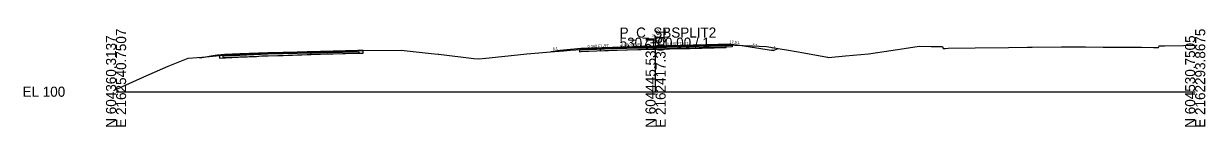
# Model space of a CAD drawing. Extents: x -26 to 1303, y -10 to 12033.
# Drawn here: x 974.3 to 1302.8, y 1490.3 to 1517.8 of the extents above; entities that cross this region are included whole.
import ezdxf

# ---------------------------------------------------------------- set-up
doc = ezdxf.new("R2010")
doc.units = 0
for name, color, linetype in [('RD_GPK_XS_Cell', 7, 'Continuous'), ('RD_XS_Base', 7, 'Continuous'), ('RD_XS_ExGround', 7, 'Continuous'), ('RD_XS_ExPaveRet', 7, 'Continuous'), ('RD_XS_Greenside', 7, 'Continuous'), ('RD_XS_Pave', 7, 'Continuous'), ('RD_XS_PaveOvlay_CP', 7, 'Continuous'), ('RD_XS_TieSlope', 7, 'Continuous'), ('RD_XS_TX_Elev_EX', 7, 'Continuous'), ('RD_XS_TX_Elev_PR', 7, 'Continuous'), ('RD_XS_TX_ShdSlope', 7, 'Continuous'), ('RD_XS_TX_Slope', 7, 'Continuous')]:
    doc.layers.add(name, color=color, linetype=linetype)

msp = doc.modelspace()

# ---------------------------------------------------------------- linework, layer by layer
at = {"layer": 'RD_GPK_XS_Cell'}
for p, q in [((1150, 1500), (1150, 1515)), ((1000, 1500), (1150, 1500)), ((1150, 1500), (1300, 1500))]:
    msp.add_line(p, q, dxfattribs=at)
at = {"layer": 'RD_XS_Base'}
for p, q in [((1129.34, 1511.62), (1128.84, 1511.6)), ((1128.84, 1511.6), (1128.84, 1511.6)), ((1128.84, 1511.6), (1128.84, 1511.1)), ((1138, 1511.97), (1129.34, 1511.62)), ((1129.34, 1511.62), (1129.34, 1511.62)), ((1129.34, 1511.12), (1138, 1511.47)), ((1150, 1512.3), (1138, 1511.97)), ((1138, 1511.97), (1138, 1511.97)), ((1138, 1511.47), (1150, 1511.8)), ((1138, 1511.47), (1138, 1511.47)), ((1150, 1512.3), (1170.78, 1512.89)), ((1150, 1511.8), (1150, 1512.46)), ((1150, 1512.46), (1150, 1512.46)), ((1150, 1512.46), (1150, 1512.46)), ((1150, 1512.46), (1150, 1512.3)), ((1171.28, 1512.4), (1150, 1511.8)), ((1150, 1512.3), (1150, 1512.3)), ((1150, 1511.8), (1150, 1512.3)), ((1150, 1512.3), (1150, 1512.3)), ((1150, 1512.3), (1150, 1512.3)), ((1150, 1511.8), (1150, 1511.8)), ((1162, 1512.64), (1162, 1512.64)), ((1162, 1512.64), (1162, 1512.64)), ((1162, 1512.14), (1162, 1512.14)), ((1162, 1512.14), (1162, 1512.14)), ((1170.78, 1512.89), (1170.78, 1512.89)), ((1171.28, 1512.9), (1171.28, 1512.4)), ((1171.28, 1512.87), (1171.28, 1512.87)), ((1029.88, 1509.98), (1029.7, 1509.97)), ((1029.7, 1509.97), (1029.7, 1509.65)), ((1029.7, 1509.65), (1029.7, 1509.47)), ((1029.7, 1509.47), (1029.88, 1509.48)), ((1030.2, 1509.99), (1029.88, 1509.98)), ((1029.88, 1509.48), (1030.2, 1509.49)), ((1034.45, 1510.16), (1030.2, 1509.99)), ((1030.2, 1509.49), (1034.45, 1509.66)), ((1042.2, 1510.47), (1034.45, 1510.16)), ((1034.45, 1509.66), (1042.2, 1509.97)), ((1046.47, 1510.58), (1042.2, 1510.47)), ((1042.2, 1509.97), (1046.47, 1510.08)), ((1054.2, 1510.78), (1046.47, 1510.58)), ((1046.47, 1510.08), (1054.2, 1510.28)), ((1054.2, 1510.78), (1067.49, 1511.07)), ((1054.2, 1510.28), (1054.2, 1510.94)), ((1054.2, 1510.94), (1054.2, 1510.94)), ((1054.2, 1510.94), (1054.2, 1510.94)), ((1054.2, 1510.94), (1054.2, 1510.78)), ((1054.2, 1510.78), (1054.2, 1510.78)), ((1054.2, 1510.28), (1054.2, 1510.78)), ((1054.2, 1510.78), (1054.2, 1510.78)), ((1054.2, 1510.78), (1054.2, 1510.78)), ((1067.49, 1510.57), (1054.2, 1510.28)), ((1054.2, 1510.28), (1054.2, 1510.28)), ((1066.99, 1511.06), (1066.99, 1511.06)), ((1067.49, 1511.07), (1067.49, 1510.57)), ((1067.49, 1511.04), (1067.49, 1511.04)), ((1067.49, 1510.54), (1067.49, 1510.54)), ((1067.49, 1510.54), (1067.49, 1510.54)), ((1128.84, 1511.1), (1129.34, 1511.12)), ((1129.34, 1511.12), (1129.34, 1511.12))]:
    msp.add_line(p, q, dxfattribs=at)
at = {"layer": 'RD_XS_ExGround'}
msp.add_lwpolyline([(1000, 1500.62), (1001.8, 1501.41), (1008.58, 1504.51), (1009.22, 1504.79), (1014.52, 1507.1), (1020.09, 1509.3), (1025.01, 1509.7), (1028.72, 1510.03), (1033.84, 1510.29), (1039.07, 1510.5), (1040.42, 1510.66), (1041.32, 1510.69), (1042.18, 1510.73), (1053.16, 1511.05), (1056.82, 1511.18), (1067.32, 1511.43), (1068.74, 1511.46), (1068.78, 1511.46), (1079.23, 1511.51), (1087.65, 1510.63), (1089.57, 1510.45), (1089.78, 1510.42), (1099.49, 1509.24), (1100.86, 1509.09), (1102.81, 1509.28), (1105.47, 1509.57), (1114.2, 1510.49), (1121.85, 1511.13), (1124.48, 1511.35), (1126.3, 1511.5), (1129.35, 1511.71), (1134.57, 1512.07), (1139.36, 1512.24), (1145.08, 1512.46), (1146.02, 1512.5), (1149.98, 1512.58), (1150.08, 1512.58), (1150.08, 1512.58), (1150.13, 1512.58), (1153.88, 1512.65), (1159.25, 1512.73), (1159.52, 1512.74), (1169.63, 1513.01), (1176.74, 1512.72), (1180.83, 1512.56), (1184.06, 1511.97), (1186.98, 1511.5), (1191.22, 1510.79), (1197.82, 1509.56), (1198.05, 1509.52), (1202.75, 1509.96), (1209.22, 1510.5), (1215.43, 1511.43), (1220.33, 1512.2), (1223.25, 1512.61), (1226.61, 1512.54), (1229.79, 1512.49), (1229.86, 1512.25), (1229.94, 1511.99), (1230.61, 1512.02), (1231.35, 1512.04), (1238.83, 1512.14), (1248.09, 1512.28), (1253.38, 1512.32), (1254.7, 1512.33), (1262.84, 1512.4), (1266.31, 1512.42), (1269.55, 1512.44), (1274.45, 1512.34), (1275.65, 1512.33), (1280.56, 1512.38), (1282.43, 1512.36), (1285.1, 1512.33), (1288.43, 1512.29), (1288.81, 1512.28), (1289.85, 1512.24), (1289.96, 1512.61), (1290, 1512.74), (1291.46, 1512.75), (1296.8, 1512.77), (1300, 1512.92)], dxfattribs=at)
at = {"layer": 'RD_XS_ExPaveRet'}
for points in [[(1068.74, 1511.46), (1068.74, 1511.46), (1068.74, 1511.46), (1067.29, 1511.43), (1067.27, 1511.43), (1056.84, 1511.18), (1056.82, 1511.18), (1053.26, 1511.05), (1053.16, 1511.05), (1042.27, 1510.73), (1042.19, 1510.73), (1041.33, 1510.69), (1041.32, 1510.69), (1040.42, 1510.66), (1040.41, 1510.66), (1039.07, 1510.5), (1039.07, 1510.5), (1033.93, 1510.3), (1033.84, 1510.29), (1028.76, 1510.04), (1028.72, 1510.03), (1028.72, 1510.03), (1028.72, 1510.03), (1028.72, 1510.02), (1028.72, 1509.28), (1028.72, 1509.28), (1028.72, 1509.28), (1028.76, 1509.29), (1033.84, 1509.54), (1033.93, 1509.55), (1039.07, 1509.75), (1039.07, 1509.75), (1040.41, 1509.91), (1040.42, 1509.91), (1041.32, 1509.94), (1041.33, 1509.94), (1042.19, 1509.98), (1042.27, 1509.98), (1053.16, 1510.3), (1053.26, 1510.3), (1056.82, 1510.43), (1056.84, 1510.43), (1067.27, 1510.68), (1067.29, 1510.68), (1068.74, 1510.71), (1068.74, 1510.71), (1068.74, 1510.71), (1068.74, 1510.71), (1068.74, 1510.71), (1068.74, 1511.46), (1068.74, 1511.46)], [(1068.74, 1511.46), (1068.74, 1511.46), (1067.29, 1511.43), (1067.27, 1511.43), (1056.84, 1511.18), (1056.82, 1511.18), (1053.26, 1511.05), (1053.16, 1511.05), (1042.27, 1510.73), (1042.19, 1510.73), (1041.33, 1510.69), (1041.32, 1510.69), (1040.42, 1510.66), (1040.41, 1510.66), (1039.07, 1510.5), (1039.07, 1510.5), (1033.93, 1510.3), (1033.84, 1510.29), (1028.76, 1510.04), (1028.72, 1510.03), (1028.72, 1510.03), (1028.72, 1510.02), (1028.72, 1509.28), (1028.72, 1509.28), (1028.76, 1509.29), (1033.84, 1509.54), (1033.93, 1509.55), (1039.07, 1509.75), (1039.07, 1509.75), (1040.41, 1509.91), (1040.42, 1509.91), (1041.32, 1509.94), (1041.33, 1509.94), (1042.19, 1509.98), (1042.27, 1509.98), (1053.16, 1510.3), (1053.26, 1510.3), (1056.82, 1510.43), (1056.84, 1510.43), (1067.27, 1510.68), (1067.29, 1510.68), (1068.74, 1510.71), (1068.74, 1510.71), (1068.74, 1510.71), (1068.74, 1510.71), (1068.74, 1511.46), (1068.74, 1511.46)], [(1169.63, 1513.01), (1159.52, 1512.74), (1159.25, 1512.73), (1159.25, 1512.73), (1153.88, 1512.65), (1153.88, 1512.65), (1150.13, 1512.58), (1150.13, 1512.58), (1150.08, 1512.58), (1150.08, 1512.58), (1149.98, 1512.58), (1146.02, 1512.5), (1146.02, 1512.5), (1145.08, 1512.46), (1145.08, 1512.46), (1145.08, 1512.46), (1139.36, 1512.24), (1139.36, 1512.24), (1134.57, 1512.07), (1134.57, 1512.07), (1134.57, 1512.07), (1134.57, 1511.32), (1134.57, 1511.32), (1139.36, 1511.49), (1139.36, 1511.49), (1145.08, 1511.71), (1145.08, 1511.71), (1145.08, 1511.71), (1146.02, 1511.75), (1146.02, 1511.75), (1149.98, 1511.83), (1150.08, 1511.83), (1150.08, 1511.83), (1150.13, 1511.83), (1150.13, 1511.83), (1153.88, 1511.9), (1153.88, 1511.9), (1159.25, 1511.98), (1159.25, 1511.98), (1159.52, 1511.99), (1169.63, 1512.26), (1169.63, 1512.26), (1169.63, 1512.26), (1169.63, 1513.01), (1169.63, 1513.01), (1169.63, 1513.01), (1169.63, 1513.01)], [(1169.63, 1513.01), (1159.52, 1512.74), (1159.25, 1512.73), (1153.88, 1512.65), (1150.13, 1512.58), (1150.08, 1512.58), (1150.08, 1512.58), (1149.98, 1512.58), (1146.02, 1512.5), (1145.08, 1512.46), (1139.36, 1512.24), (1134.57, 1512.07), (1134.57, 1512.07), (1134.57, 1511.32), (1134.57, 1511.32), (1139.36, 1511.49), (1145.08, 1511.71), (1146.02, 1511.75), (1149.98, 1511.83), (1150.08, 1511.83), (1150.08, 1511.83), (1150.13, 1511.83), (1153.88, 1511.9), (1159.25, 1511.98), (1159.52, 1511.99), (1169.63, 1512.26), (1169.63, 1513.01)]]:
    msp.add_lwpolyline(points, dxfattribs=at)
at = {"layer": 'RD_XS_Greenside'}
for p, q in [((1123.34, 1511.46), (1120.9, 1511.05)), ((1172.78, 1513.04), (1182.78, 1511.38)), ((1182.78, 1511.38), (1184, 1511.99)), ((1023.35, 1509.34), (1023.31, 1509.36)), ((1026.89, 1509.93), (1023.35, 1509.34)), ((1028.2, 1510.15), (1026.89, 1509.93))]:
    msp.add_line(p, q, dxfattribs=at)
at = {"layer": 'RD_XS_Pave'}
for p, q in [((1066.99, 1511.38), (1054.2, 1511.1)), ((1066.99, 1511.22), (1066.99, 1511.38)), ((1066.99, 1511.38), (1066.99, 1511.38)), ((1138, 1512.29), (1129.34, 1511.94)), ((1129.34, 1511.78), (1138, 1512.13)), ((1138, 1512.13), (1129.34, 1511.78)), ((1129.34, 1511.62), (1138, 1511.97)), ((1129.34, 1511.94), (1129.34, 1511.94)), ((1129.34, 1511.94), (1129.34, 1511.78)), ((1129.34, 1511.78), (1129.34, 1511.78)), ((1129.34, 1511.78), (1129.34, 1511.62)), ((1150, 1512.62), (1138, 1512.29)), ((1138, 1512.13), (1150, 1512.46)), ((1150, 1512.46), (1138, 1512.13)), ((1138, 1511.97), (1150, 1512.3)), ((1138, 1512.29), (1138, 1512.29)), ((1138, 1512.13), (1138, 1512.13)), ((1138, 1512.13), (1138, 1512.13)), ((1138, 1511.97), (1138, 1511.97)), ((1170.78, 1513.2), (1150, 1512.62)), ((1170.78, 1513.05), (1150, 1512.46)), ((1150, 1512.46), (1170.78, 1513.05)), ((1150, 1512.3), (1171.28, 1512.9)), ((1150, 1512.62), (1150, 1512.62)), ((1150, 1512.46), (1150, 1512.46)), ((1150, 1512.46), (1150, 1512.46)), ((1150, 1512.46), (1150, 1512.3)), ((1150, 1512.46), (1150, 1512.46)), ((1150, 1512.3), (1150, 1512.46)), ((1150, 1512.46), (1150, 1512.46)), ((1150, 1512.46), (1150, 1512.46)), ((1150, 1512.3), (1150, 1512.3)), ((1150, 1512.3), (1150, 1512.3)), ((1162, 1512.96), (1162, 1512.96)), ((1162, 1512.96), (1162, 1512.96)), ((1162, 1512.8), (1162, 1512.8)), ((1162, 1512.8), (1162, 1512.8)), ((1162, 1512.8), (1162, 1512.8)), ((1162, 1512.8), (1162, 1512.8)), ((1162, 1512.64), (1162, 1512.64)), ((1162, 1512.64), (1162, 1512.64)), ((1170.78, 1513.05), (1170.78, 1513.2)), ((1170.78, 1513.2), (1170.78, 1513.2)), ((1170.78, 1512.89), (1170.78, 1513.05)), ((1170.78, 1513.05), (1170.78, 1513.05)), ((1034.45, 1510.48), (1030.2, 1510.31)), ((1030.2, 1510.15), (1034.45, 1510.32)), ((1034.45, 1510.32), (1030.2, 1510.15)), ((1030.2, 1510.31), (1030.2, 1510.2)), ((1030.2, 1510.2), (1030.2, 1510.15)), ((1030.2, 1509.99), (1034.45, 1510.16)), ((1030.2, 1510.15), (1030.2, 1510.05)), ((1030.2, 1510.05), (1030.2, 1509.99)), ((1042.2, 1510.79), (1034.45, 1510.48)), ((1034.45, 1510.32), (1042.2, 1510.63)), ((1042.2, 1510.63), (1034.45, 1510.32)), ((1034.45, 1510.16), (1042.2, 1510.47)), ((1046.47, 1510.9), (1042.2, 1510.79)), ((1042.2, 1510.63), (1046.47, 1510.74)), ((1046.47, 1510.74), (1042.2, 1510.63)), ((1042.2, 1510.47), (1046.47, 1510.58)), ((1054.2, 1511.1), (1046.47, 1510.9)), ((1046.47, 1510.74), (1054.2, 1510.94)), ((1054.2, 1510.94), (1046.47, 1510.74)), ((1046.47, 1510.58), (1054.2, 1510.78)), ((1066.99, 1511.22), (1054.2, 1510.94)), ((1054.2, 1510.94), (1066.99, 1511.22)), ((1054.2, 1511.1), (1054.2, 1511.1)), ((1054.2, 1510.78), (1066.99, 1511.06)), ((1054.2, 1510.94), (1054.2, 1510.94)), ((1054.2, 1510.94), (1054.2, 1510.94)), ((1054.2, 1510.94), (1054.2, 1510.78)), ((1054.2, 1510.94), (1054.2, 1510.94)), ((1054.2, 1510.78), (1054.2, 1510.94)), ((1054.2, 1510.94), (1054.2, 1510.94)), ((1054.2, 1510.94), (1054.2, 1510.94)), ((1054.2, 1510.78), (1054.2, 1510.78)), ((1054.2, 1510.78), (1054.2, 1510.78)), ((1066.99, 1511.06), (1066.99, 1511.22)), ((1066.99, 1511.22), (1066.99, 1511.22)), ((1066.99, 1511.22), (1066.99, 1511.22)), ((1066.99, 1511.22), (1066.99, 1511.22)), ((1066.99, 1511.06), (1066.99, 1511.06)), ((1066.99, 1511.06), (1066.99, 1511.06))]:
    msp.add_line(p, q, dxfattribs=at)
at = {"layer": 'RD_XS_PaveOvlay_CP'}
for p, q in [((1066.99, 1511.38), (1054.2, 1511.1)), ((1066.99, 1511.38), (1066.99, 1511.38)), ((1138, 1512.29), (1129.34, 1511.94)), ((1150, 1512.62), (1138, 1512.29)), ((1138, 1512.29), (1138, 1512.29)), ((1170.78, 1513.2), (1150, 1512.62)), ((1150, 1512.62), (1150, 1512.62)), ((1162, 1512.96), (1162, 1512.96)), ((1162, 1512.96), (1162, 1512.96)), ((1034.45, 1510.48), (1030.2, 1510.31)), ((1042.2, 1510.79), (1034.45, 1510.48)), ((1046.47, 1510.9), (1042.2, 1510.79)), ((1054.2, 1511.1), (1046.47, 1510.9)), ((1054.2, 1511.1), (1054.2, 1511.1))]:
    msp.add_line(p, q, dxfattribs=at)
at = {"layer": 'RD_XS_TieSlope'}
for p, q in [((1129.34, 1511.94), (1123.34, 1511.46)), ((1170.78, 1513.2), (1172.78, 1513.04)), ((1030.2, 1510.31), (1028.2, 1510.15))]:
    msp.add_line(p, q, dxfattribs=at)

# ---------------------------------------------------------------- texts
at = {"layer": 'RD_GPK_XS_Cell'}
for s, p in [('P_C_SBSPLIT2', (1140, 1515)), ('5307+00.00 / 1', (1140, 1512.2)), ('EL 100', (974, 1498.6))]:
    msp.add_text(s, height=2.8, dxfattribs=at).set_placement(p)
for s, p in [('N 604360.3137', (1000, 1490)), ('E 2162540.7507', (1002.8, 1490)), ('N 604445.5321', (1150, 1490)), ('E 2162417.3091', (1152.8, 1490)), ('N 604530.7505', (1300, 1490)), ('E 2162293.8675', (1302.8, 1490))]:
    msp.add_text(s, height=2.8, rotation=90, dxfattribs=at).set_placement(p)
at = {"layer": 'RD_XS_TX_Elev_EX'}
msp.add_text('112.58', height=0.6, rotation=90, dxfattribs=at).set_placement((1149.72, 1513.46))
at = {"layer": 'RD_XS_TX_Elev_PR'}
msp.add_text('112.62', height=1, rotation=90, dxfattribs=at).set_placement((1151.29, 1513.1))
at = {"layer": 'RD_XS_TX_ShdSlope'}
msp.add_text('12.5:1', height=0.75, rotation=355.4261, dxfattribs=at).set_placement((1170.52, 1513.46))
at = {"layer": 'RD_XS_TX_Slope'}
for s, rotation, p in [('6:1', 9.4623, (1121.46, 1511.47)), ('0.040 FT./FT.', 2.2906, (1131.1, 1512.17)), ('0.030 FT./FT.', 1.7184, (1140.41, 1512.57)), ('0.030 FT./FT.', 1.7184, (1153.16, 1512.84)), ('6:1', 350.5358, (1176.91, 1512.68)), ('2:1', 26.5651, (1182.27, 1511.49))]:
    msp.add_text(s, height=0.75, rotation=rotation, dxfattribs=at).set_placement(p)

doc.saveas('drawing.dxf')
